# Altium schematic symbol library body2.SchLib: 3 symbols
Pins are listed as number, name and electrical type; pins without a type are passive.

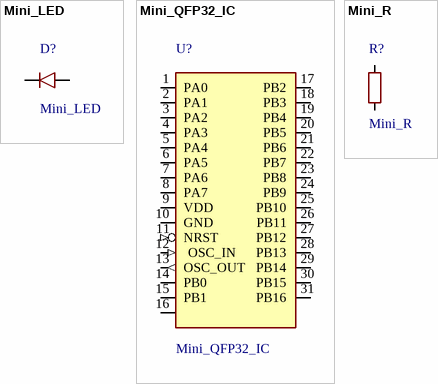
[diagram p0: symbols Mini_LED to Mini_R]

## Mini_LED
designator D?
Mini light emitting diode. Fenolite test symbol
footprint Mini_LED_THT_3mm
pins: 1 K, 2 A

## Mini_QFP32_IC
designator U?
Mini 32-pin IC. Fenolite test symbol
footprint Mini_QFP-32_7x7mm_P0.8mm
pins: 1 PA0 (io), 2 PA1 (io), 3 PA2 (io), 4 PA3 (io), 5 PA4 (io), 6 PA5 (io), 7 PA6 (io), 8 PA7 (io), 9 VDD (power), 10 GND (power), 11 NRST (in), 12 OSC_IN (in), 13 OSC_OUT (out), 14 PB0 (io), 15 PB1 (hiz), 16, 17 PB2 (io), 18 PB3 (io), 19 PB4 (io), 20 PB5 (io), 21 PB6 (io), 22 PB7 (io), 23 PB8 (io), 24 PB9 (io), 25 PB10 (io), 26 PB11 (io), 27 PB12 (io), 28 PB13 (io), 29 PB14 (io), 30 PB15 (io), 31 PB16 (io), 32 EP hidden

## Mini_R
designator R?
Mini resistor. Fenolite test symbol
footprint Mini_R_0603
pins: 1, 2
